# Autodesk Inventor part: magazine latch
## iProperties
Created: 2006-04
Part Number: magazine latch
Document SubType Name: Modeling
Designer: Калинин
Author: Калинин
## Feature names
1. Выдавливание1 [Extrusion]
2. Выдавливание2 [Extrusion]
3. Выдавливание3 [Extrusion]
4. Выдавливание4 [Extrusion]
5. Выдавливание5 [Extrusion]
6. Выдавливание6 [Extrusion]
7. Сопряжение1 [Fillet]
8. Сопряжение2 [Fillet]
9. Сопряжение3 [Fillet]
10. Сопряжение4 [Fillet]
11. Сопряжение5 [Fillet]
